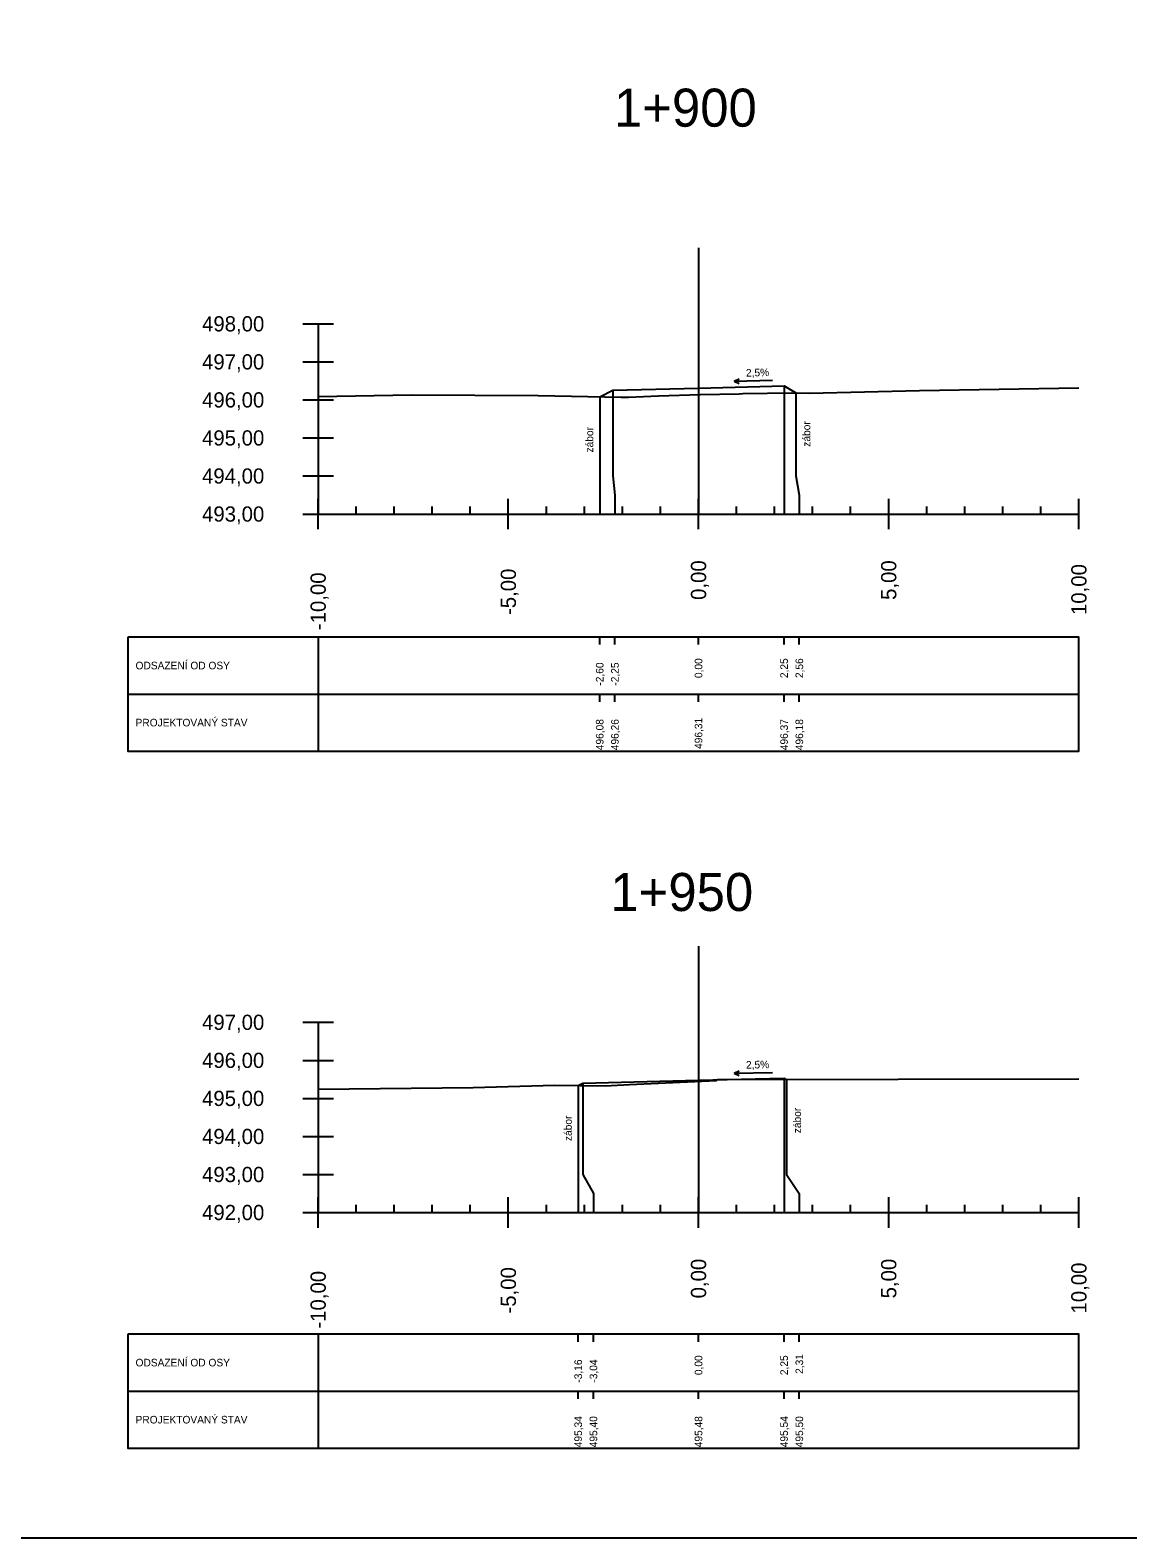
# Model space of a CAD drawing. Extents: x -631407 to -631215, y -1089700 to -1088598.
# Drawn here: x -631287.77 to -631258.91, y -1089270.8 to -1089231.17 of the extents above; entities that cross this region are included whole.
import ezdxf

# ---------------------------------------------------------------- set-up
doc = ezdxf.new("R2010")
doc.units = 0
for name, color, linetype in [('08_LEGENDA_HV', 7, 'Continuous'), ('59', 7, 'Continuous'), ('NIVELETA_VYSKY', 7, 'Continuous'), ('REZ_BODY', 7, 'Continuous'), ('REZ_ODSTUPY', 7, 'Continuous'), ('REZ_POPIS', 7, 'Continuous'), ('REZ_RAMY', 7, 'Continuous'), ('REZ_STANICENI', 7, 'Continuous'), ('REZ_SVISLE', 7, 'Continuous'), ('REZ_TENKA', 7, 'Continuous'), ('REZ_TLUSTA', 7, 'Continuous'), ('TABULKA_POPIS', 7, 'Continuous'), ('TEREN', 7, 'Continuous'), ('zábor', 7, 'Continuous')]:
    doc.layers.add(name, color=color, linetype=linetype)

msp = doc.modelspace()

# ---------------------------------------------------------------- linework, layer by layer
at = {"layer": '08_LEGENDA_HV'}
msp.add_lwpolyline([(-631215.384, -1089270.801), (-631215.384, -1089110.964), (-631407.014, -1089110.964), (-631407.014, -1089270.801)], close=True, dxfattribs=at)
at = {"layer": '59'}
for p, q in [((-631280.602, -1089238.886), (-631279.802, -1089238.886)), ((-631280.202, -1089238.886), (-631280.202, -1089243.886)), ((-631280.602, -1089239.886), (-631279.802, -1089239.886)), ((-631280.602, -1089240.886), (-631279.802, -1089240.886)), ((-631280.602, -1089241.886), (-631279.802, -1089241.886)), ((-631280.602, -1089242.886), (-631279.802, -1089242.886)), ((-631280.602, -1089243.886), (-631279.802, -1089243.886)), ((-631280.602, -1089257.248), (-631279.802, -1089257.248)), ((-631280.202, -1089257.248), (-631280.202, -1089262.248)), ((-631280.602, -1089258.248), (-631279.802, -1089258.248)), ((-631280.602, -1089259.248), (-631279.802, -1089259.248)), ((-631280.602, -1089260.248), (-631279.802, -1089260.248)), ((-631280.602, -1089261.248), (-631279.802, -1089261.248)), ((-631280.602, -1089262.248), (-631279.802, -1089262.248))]:
    msp.add_line(p, q, dxfattribs=at)
at = {"layer": 'REZ_RAMY'}
for p, q in [((-631285.202, -1089247.119), (-631285.202, -1089250.119)), ((-631280.202, -1089247.119), (-631280.202, -1089250.119)), ((-631272.8, -1089247.319), (-631272.8, -1089247.119)), ((-631272.4, -1089247.319), (-631272.4, -1089247.119)), ((-631270.202, -1089247.319), (-631270.202, -1089247.119)), ((-631267.952, -1089247.319), (-631267.952, -1089247.119)), ((-631267.552, -1089247.319), (-631267.552, -1089247.119)), ((-631285.202, -1089248.619), (-631260.202, -1089248.619)), ((-631272.8, -1089248.819), (-631272.8, -1089248.619)), ((-631272.4, -1089248.819), (-631272.4, -1089248.619)), ((-631270.202, -1089248.819), (-631270.202, -1089248.619)), ((-631267.952, -1089248.819), (-631267.952, -1089248.619)), ((-631267.552, -1089248.819), (-631267.552, -1089248.619)), ((-631285.202, -1089265.444), (-631285.202, -1089268.444)), ((-631280.202, -1089265.444), (-631280.202, -1089268.444)), ((-631273.365, -1089265.644), (-631273.365, -1089265.444)), ((-631272.965, -1089265.644), (-631272.965, -1089265.444)), ((-631270.202, -1089265.644), (-631270.202, -1089265.444)), ((-631267.952, -1089265.644), (-631267.952, -1089265.444)), ((-631267.552, -1089265.644), (-631267.552, -1089265.444)), ((-631285.202, -1089266.944), (-631260.202, -1089266.944)), ((-631273.365, -1089267.144), (-631273.365, -1089266.944)), ((-631272.965, -1089267.144), (-631272.965, -1089266.944)), ((-631270.202, -1089267.144), (-631270.202, -1089266.944)), ((-631267.952, -1089267.144), (-631267.952, -1089266.944)), ((-631267.552, -1089267.144), (-631267.552, -1089266.944))]:
    msp.add_line(p, q, dxfattribs=at)
for points in [[(-631285.202, -1089247.119), (-631285.202, -1089250.119), (-631260.202, -1089250.119), (-631260.202, -1089247.119)], [(-631285.202, -1089265.444), (-631285.202, -1089268.444), (-631260.202, -1089268.444), (-631260.202, -1089265.444)]]:
    msp.add_lwpolyline(points, close=True, dxfattribs=at)
at = {"layer": 'REZ_SVISLE'}
for points in [[(-631267.952, -1089240.518), (-631267.952, -1089242.886), (-631267.952, -1089243.386), (-631267.952, -1089243.886)], [(-631272.8, -1089240.805), (-631272.8, -1089242.886), (-631272.8, -1089243.386), (-631272.8, -1089243.886)], [(-631272.452, -1089240.631), (-631272.452, -1089242.886), (-631272.4, -1089243.386), (-631272.4, -1089243.886)], [(-631270.202, -1089240.574), (-631270.202, -1089242.886), (-631270.202, -1089243.386), (-631270.202, -1089243.886)], [(-631267.646, -1089240.701), (-631267.646, -1089242.886), (-631267.552, -1089243.386), (-631267.552, -1089243.886)], [(-631270.202, -1089258.769), (-631270.202, -1089261.248), (-631270.202, -1089261.748), (-631270.202, -1089262.248)], [(-631267.952, -1089258.713), (-631267.952, -1089261.248), (-631267.952, -1089261.748), (-631267.952, -1089262.248)], [(-631267.89, -1089258.749), (-631267.89, -1089261.248), (-631267.552, -1089261.748), (-631267.552, -1089262.248)], [(-631273.365, -1089258.907), (-631273.365, -1089261.248), (-631273.365, -1089261.748), (-631273.365, -1089262.248)], [(-631273.242, -1089258.845), (-631273.242, -1089261.248), (-631272.965, -1089261.748), (-631272.965, -1089262.248)]]:
    msp.add_lwpolyline(points, dxfattribs=at)
at = {"layer": 'REZ_TENKA'}
for p, q in [((-631279.202, -1089243.886), (-631279.202, -1089243.686)), ((-631278.202, -1089243.886), (-631278.202, -1089243.686)), ((-631277.202, -1089243.886), (-631277.202, -1089243.686)), ((-631276.202, -1089243.886), (-631276.202, -1089243.686)), ((-631274.202, -1089243.886), (-631274.202, -1089243.686)), ((-631273.202, -1089243.886), (-631273.202, -1089243.686)), ((-631272.202, -1089243.886), (-631272.202, -1089243.686)), ((-631271.202, -1089243.886), (-631271.202, -1089243.686)), ((-631269.202, -1089243.886), (-631269.202, -1089243.686)), ((-631268.202, -1089243.886), (-631268.202, -1089243.686)), ((-631267.202, -1089243.886), (-631267.202, -1089243.686)), ((-631266.202, -1089243.886), (-631266.202, -1089243.686)), ((-631264.202, -1089243.886), (-631264.202, -1089243.686)), ((-631263.202, -1089243.886), (-631263.202, -1089243.686)), ((-631262.202, -1089243.886), (-631262.202, -1089243.686)), ((-631261.202, -1089243.886), (-631261.202, -1089243.686)), ((-631279.202, -1089262.248), (-631279.202, -1089262.048)), ((-631278.202, -1089262.248), (-631278.202, -1089262.048)), ((-631277.202, -1089262.248), (-631277.202, -1089262.048)), ((-631276.202, -1089262.248), (-631276.202, -1089262.048)), ((-631274.202, -1089262.248), (-631274.202, -1089262.048)), ((-631273.202, -1089262.248), (-631273.202, -1089262.048)), ((-631272.202, -1089262.248), (-631272.202, -1089262.048)), ((-631271.202, -1089262.248), (-631271.202, -1089262.048)), ((-631269.202, -1089262.248), (-631269.202, -1089262.048)), ((-631268.202, -1089262.248), (-631268.202, -1089262.048)), ((-631267.202, -1089262.248), (-631267.202, -1089262.048)), ((-631266.202, -1089262.248), (-631266.202, -1089262.048)), ((-631264.202, -1089262.248), (-631264.202, -1089262.048)), ((-631263.202, -1089262.248), (-631263.202, -1089262.048)), ((-631262.202, -1089262.248), (-631262.202, -1089262.048)), ((-631261.202, -1089262.248), (-631261.202, -1089262.048))]:
    msp.add_line(p, q, dxfattribs=at)
at = {"layer": 'REZ_TLUSTA'}
for p, q in [((-631270.202, -1089236.886), (-631270.202, -1089243.886)), ((-631280.202, -1089244.286), (-631280.202, -1089243.486)), ((-631275.202, -1089244.286), (-631275.202, -1089243.486)), ((-631270.202, -1089244.286), (-631270.202, -1089243.486)), ((-631265.202, -1089244.286), (-631265.202, -1089243.486)), ((-631260.202, -1089244.286), (-631260.202, -1089243.486)), ((-631280.202, -1089243.886), (-631260.202, -1089243.886)), ((-631270.202, -1089255.248), (-631270.202, -1089262.248)), ((-631280.202, -1089262.648), (-631280.202, -1089261.848)), ((-631275.202, -1089262.648), (-631275.202, -1089261.848)), ((-631270.202, -1089262.648), (-631270.202, -1089261.848)), ((-631265.202, -1089262.648), (-631265.202, -1089261.848)), ((-631260.202, -1089262.648), (-631260.202, -1089261.848)), ((-631280.202, -1089262.248), (-631260.202, -1089262.248))]:
    msp.add_line(p, q, dxfattribs=at)
at = {"layer": 'TEREN'}
for points in [[(-631272.8, -1089240.805), (-631272.452, -1089240.631), (-631270.202, -1089240.574), (-631267.952, -1089240.518), (-631267.646, -1089240.701)], [(-631280.202, -1089240.8), (-631277.746, -1089240.754), (-631274.415, -1089240.773), (-631272.232, -1089240.816), (-631272.047, -1089240.818), (-631271.256, -1089240.778), (-631270.158, -1089240.744), (-631269.132, -1089240.728), (-631269.037, -1089240.721), (-631267.748, -1089240.699), (-631267.28, -1089240.709), (-631264.39, -1089240.637), (-631260.202, -1089240.568)], [(-631280.202, -1089259.005), (-631276.126, -1089258.958), (-631273.976, -1089258.897), (-631272.659, -1089258.918), (-631272.02, -1089258.885), (-631269.733, -1089258.781), (-631269.703, -1089258.753), (-631260.202, -1089258.732)], [(-631273.365, -1089258.907), (-631273.242, -1089258.845), (-631270.202, -1089258.769), (-631267.952, -1089258.713), (-631267.89, -1089258.749)]]:
    msp.add_lwpolyline(points, dxfattribs=at)
at = {"layer": 'zábor'}
for p, q in [((-631269.269, -1089240.395), (-631269.132, -1089240.33)), ((-631269.269, -1089240.395), (-631268.261, -1089240.37)), ((-631269.269, -1089240.395), (-631269.129, -1089240.452)), ((-631269.269, -1089258.589), (-631269.132, -1089258.525)), ((-631269.269, -1089258.589), (-631268.261, -1089258.564)), ((-631269.269, -1089258.589), (-631269.129, -1089258.647))]:
    msp.add_line(p, q, dxfattribs=at)

# ---------------------------------------------------------------- texts
at = {"layer": 'NIVELETA_VYSKY'}
for s, p in [('496,31', (-631270.102, -1089250.062)), ('496,08', (-631272.7, -1089250.095)), ('496,26', (-631272.3, -1089250.095)), ('496,37', (-631267.852, -1089250.095)), ('496,18', (-631267.452, -1089250.095)), ('495,34', (-631273.265, -1089268.42)), ('495,40', (-631272.865, -1089268.42)), ('495,48', (-631270.102, -1089268.42)), ('495,54', (-631267.852, -1089268.42)), ('495,50', (-631267.452, -1089268.42))]:
    msp.add_text(s, height=0.2, rotation=90, dxfattribs=at).set_placement(p)
at = {"layer": 'REZ_BODY'}
for s, p in [('-2,60', (-631272.7, -1089248.397)), ('-2,25', (-631272.3, -1089248.397)), ('0,00', (-631270.102, -1089248.199)), ('2,25', (-631267.852, -1089248.199)), ('2,56', (-631267.452, -1089248.199)), ('-3,16', (-631273.265, -1089266.721)), ('-3,04', (-631272.865, -1089266.721)), ('0,00', (-631270.102, -1089266.523)), ('2,25', (-631267.852, -1089266.523)), ('2,31', (-631267.452, -1089266.49))]:
    msp.add_text(s, height=0.2, rotation=90, dxfattribs=at).set_placement(p)
at = {"layer": 'REZ_ODSTUPY'}
for s, p in [('0,00', (-631270.002, -1089246.144)), ('5,00', (-631265.002, -1089246.144)), ('10,00', (-631260.002, -1089246.541)), ('-10,00', (-631280.002, -1089246.938)), ('-5,00', (-631275.002, -1089246.541)), ('0,00', (-631270.002, -1089264.506)), ('5,00', (-631265.002, -1089264.506)), ('-10,00', (-631280.002, -1089265.3)), ('-5,00', (-631275.002, -1089264.903)), ('10,00', (-631260.002, -1089264.903))]:
    msp.add_text(s, height=0.4, rotation=90, dxfattribs=at).set_placement(p)
at = {"layer": 'REZ_POPIS'}
for s, p in [('498,00', (-631283.254, -1089239.086)), ('497,00', (-631283.254, -1089240.086)), ('496,00', (-631283.254, -1089241.086)), ('495,00', (-631283.254, -1089242.086)), ('494,00', (-631283.254, -1089243.086)), ('493,00', (-631283.254, -1089244.086)), ('497,00', (-631283.254, -1089257.448)), ('496,00', (-631283.254, -1089258.448)), ('495,00', (-631283.254, -1089259.448)), ('494,00', (-631283.254, -1089260.448)), ('493,00', (-631283.254, -1089261.448)), ('492,00', (-631283.254, -1089262.448))]:
    msp.add_text(s, height=0.4, dxfattribs=at).set_placement(p)
at = {"layer": 'REZ_STANICENI'}
for s, p in [('1+900', (-631272.425, -1089233.703)), ('1+950', (-631272.52, -1089254.322))]:
    msp.add_text(s, height=1, dxfattribs=at).set_placement(p)
at = {"layer": 'TABULKA_POPIS'}
for s, p in [('ODSAZENÍ OD OSY', (-631285.002, -1089247.969)), ('PROJEKTOVANÝ STAV', (-631285.002, -1089249.469)), ('ODSAZENÍ OD OSY', (-631285.002, -1089266.294)), ('PROJEKTOVANÝ STAV', (-631285.002, -1089267.794))]:
    msp.add_text(s, height=0.2, dxfattribs=at).set_placement(p)
at = {"layer": 'zábor'}
for s, rotation, p in [('2,5%', 1.4321, (-631268.952, -1089240.274)), ('zábor', 90, (-631272.97, -1089242.268)), ('zábor', 90, (-631267.264, -1089242.116)), ('2,5%', 1.4321, (-631268.952, -1089258.468)), ('zábor', 90, (-631267.508, -1089260.164)), ('zábor', 90, (-631273.535, -1089260.37))]:
    msp.add_text(s, height=0.2, rotation=rotation, dxfattribs=at).set_placement(p)

doc.saveas('drawing.dxf')
